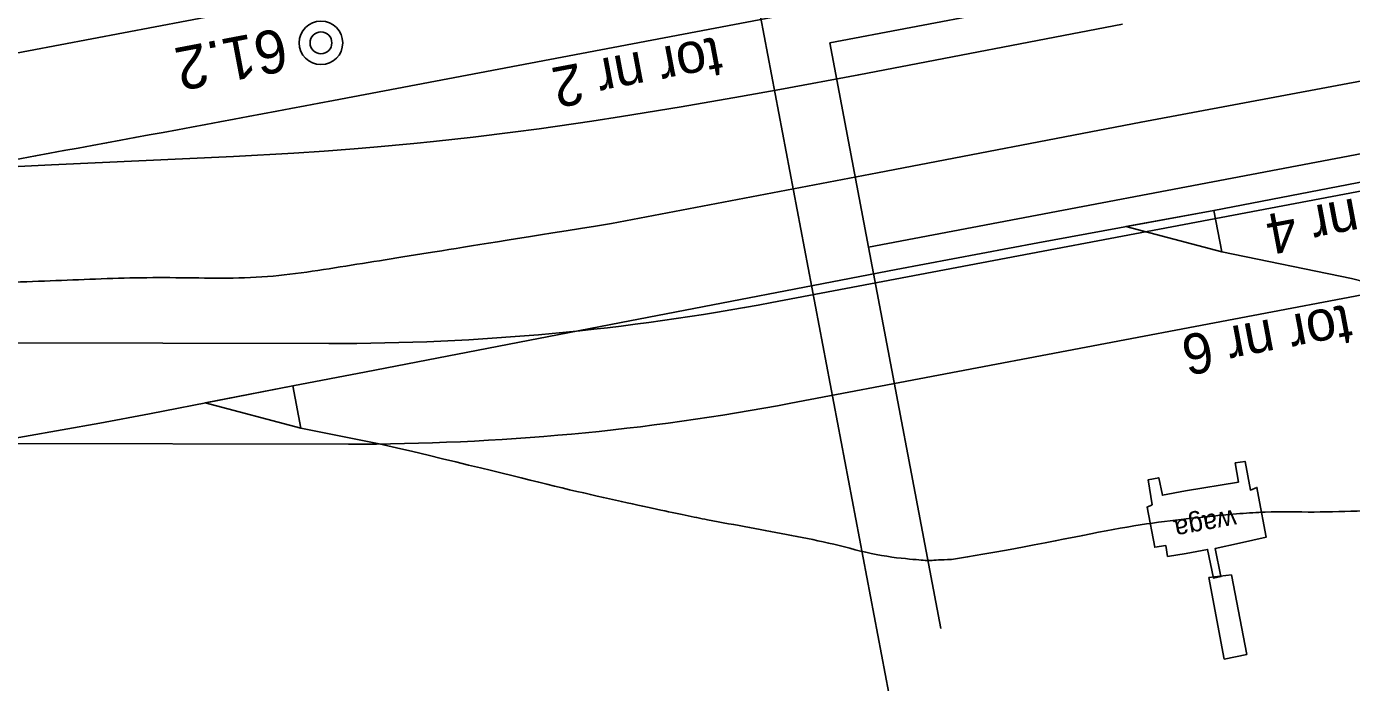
# Model space of a CAD drawing. Extents: x 6541740 to 6566395, y 5525066 to 5530361.
# Drawn here: x 6557260.7 to 6557322.2, y 5526148.2 to 5526178.6 of the extents above; entities that cross this region are included whole.
import ezdxf

# ---------------------------------------------------------------- set-up
doc = ezdxf.new("R2010")
doc.units = 0
for name, color, linetype in [('Domyślna', 7, 'Continuous'), ('ps_wymiarowanie', 7, 'Continuous'), ('TOR_PRZEK_P-komponent', 7, 'Continuous'), ('TOR_PRZEK_P-pomoc', 7, 'Continuous'), ('TOR_PRZEK_P-teren istniejacy', 7, 'Continuous'), ('TOR_PS_ODW-odwodnienie liniowe', 7, 'Continuous'), ('TOR_PS_OPIS_T-opis geometrii-wzdluz_cz torowa', 7, 'Continuous'), ('TOR_PS_T-rowy otwarte nieumocnione', 7, 'Continuous'), ('TOR_RAMKI-ramka+tabelka 1', 7, 'Continuous')]:
    doc.layers.add(name, color=color, linetype=linetype)

# ---------------------------------------------------------------- blocks, each defined once
blk = doc.blocks.new('4010_1')
at = {"layer": 'Domyślna'}
for radius in [0.75, 0.375]:
    blk.add_circle((0, 0), radius, dxfattribs=at)
blk = doc.blocks.new('X KM right')
at = {"layer": 'Domyślna'}
blk.add_line((0, 0), (-16, 0), dxfattribs=at)

msp = doc.modelspace()

# ---------------------------------------------------------------- linework, layer by layer
at = {"layer": 'ps_wymiarowanie'}
for p, q in [((6557315.566, 5526153.102), (6557316.63, 5526153.216)), ((6557315.566, 5526153.102), (6557316.63, 5526153.216)), ((6557316.287, 5526149.311), (6557315.566, 5526153.102)), ((6557316.287, 5526149.311), (6557315.566, 5526153.102)), ((6557316.63, 5526153.216), (6557317.338, 5526149.522)), ((6557316.63, 5526153.216), (6557317.338, 5526149.522)), ((6557317.338, 5526149.522), (6557316.287, 5526149.311)), ((6557317.338, 5526149.522), (6557316.287, 5526149.311))]:
    msp.add_line(p, q, dxfattribs=at)
msp.add_lwpolyline([(6557317.88, 5526156.857), (6557317.805, 5526157.272), (6557317.502, 5526157.146), (6557317.249, 5526158.48), (6557316.794, 5526158.404), (6557316.946, 5526157.519), (6557314.491, 5526157.109), (6557313.419, 5526156.911), (6557313.25, 5526157.717), (6557312.75, 5526157.619), (6557312.94, 5526156.468), (6557312.707, 5526156.36), (6557313.062, 5526154.499), (6557313.572, 5526154.571), (6557313.66, 5526154.074), (6557314.515, 5526154.202), (6557315.514, 5526154.398), (6557315.786, 5526153.071), (6557316.134, 5526153.134), (6557315.87, 5526154.446), (6557316.988, 5526154.684), (6557318.231, 5526154.972)], close=True, dxfattribs=at)
msp.add_lwpolyline([(6557317.88, 5526156.857), (6557317.805, 5526157.272), (6557317.502, 5526157.146), (6557317.249, 5526158.48), (6557316.794, 5526158.404), (6557316.946, 5526157.519), (6557314.491, 5526157.109), (6557313.419, 5526156.911), (6557313.25, 5526157.717), (6557312.75, 5526157.619), (6557312.94, 5526156.468), (6557312.707, 5526156.36), (6557313.062, 5526154.499), (6557313.572, 5526154.571), (6557313.66, 5526154.074), (6557314.515, 5526154.202), (6557315.514, 5526154.398), (6557315.786, 5526153.071), (6557316.134, 5526153.134), (6557315.87, 5526154.446), (6557316.988, 5526154.684), (6557318.231, 5526154.972)], close=True, dxfattribs=at)
at = {"layer": 'TOR_PRZEK_P-komponent'}
for p, q in [((6557416.454, 5526207.025), (6557145.327, 5526155.632)), ((6557373.207, 5526193.841), (6557274.957, 5526175.217)), ((6557371.775, 5526180.338), (6557295.3, 5526165.841)), ((6557367.242, 5526174.644), (6557296.184, 5526161.174)), ((6557274.738, 5526163.945), (6557256.935, 5526163.977)), ((6557275.656, 5526159.278), (6557256.053, 5526159.308))]:
    msp.add_line(p, q, dxfattribs=at)
msp.add_arc((6556891.406, 5528198.665), 2059.479, 280.137444, 280.733239, dxfattribs=at)
for centre, start_param in [((6556974.973, 5527855.75), 3.093771), ((6556975.857, 5527851.083), 3.093849)]:
    msp.add_ellipse(centre, major_axis=(-320.327, 1689.908), ratio=0.25, start_param=start_param, end_param=3.141593, dxfattribs=at)
at = {"layer": 'TOR_PRZEK_P-pomoc'}
for p, q in [((6557347.117, 5526187.205), (6557297.992, 5526177.893)), ((6557347.117, 5526187.205), (6557297.992, 5526177.893)), ((6557297.992, 5526177.893), (6557299.789, 5526168.412)), ((6557297.992, 5526177.893), (6557299.789, 5526168.412)), ((6557299.789, 5526168.412), (6557348.915, 5526177.724)), ((6557299.789, 5526168.412), (6557348.915, 5526177.724))]:
    msp.add_line(p, q, dxfattribs=at)
at = {"layer": 'TOR_PS_OPIS_T-opis geometrii-wzdluz_cz torowa'}
msp.add_line((6557294.428, 5526180.966), (6557304.996, 5526125.216), dxfattribs=at)
at = {"layer": 'TOR_PS_T-rowy otwarte nieumocnione'}
for p, q in [((6557307.636, 5526168.616), (6557315.806, 5526170.117)), ((6557307.636, 5526168.616), (6557315.806, 5526170.117)), ((6557307.636, 5526168.616), (6557315.806, 5526170.117)), ((6557307.636, 5526168.616), (6557315.806, 5526170.117)), ((6557307.636, 5526168.616), (6557315.806, 5526170.117)), ((6557307.636, 5526168.616), (6557315.806, 5526170.117)), ((6557311.721, 5526169.367), (6557316.167, 5526168.203)), ((6557311.721, 5526169.367), (6557316.167, 5526168.203)), ((6557311.721, 5526169.367), (6557316.167, 5526168.203)), ((6557311.721, 5526169.367), (6557316.167, 5526168.203)), ((6557322.19, 5526166.954), (6557329.385, 5526165.171)), ((6557322.19, 5526166.954), (6557329.385, 5526165.171)), ((6557322.19, 5526166.954), (6557329.385, 5526165.171)), ((6557322.19, 5526166.954), (6557329.385, 5526165.171)), ((6557266.418, 5526160.691), (6557273.08, 5526161.976)), ((6557266.418, 5526160.691), (6557273.08, 5526161.976)), ((6557266.418, 5526160.691), (6557273.08, 5526161.975)), ((6557266.418, 5526160.691), (6557273.08, 5526161.975)), ((6557266.418, 5526160.691), (6557273.08, 5526161.975)), ((6557266.418, 5526160.691), (6557273.08, 5526161.975)), ((6557269.001, 5526161.19), (6557273.446, 5526160.026)), ((6557273.446, 5526160.026), (6557269.001, 5526161.19)), ((6557269.001, 5526161.19), (6557273.446, 5526160.026)), ((6557273.446, 5526160.026), (6557269.001, 5526161.19))]:
    msp.add_line(p, q, dxfattribs=at)
for points in [[(6557300.206, 5526171.864), (6557312.429, 5526174.21), (6557325.573, 5526176.668), (6557335.79, 5526178.59), (6557342.216, 5526179.762)], [(6557300.206, 5526171.864), (6557312.429, 5526174.21), (6557325.573, 5526176.668), (6557335.79, 5526178.59), (6557342.216, 5526179.762)], [(6557311.559, 5526178.754), (6557299.33, 5526176.411), (6557299.329, 5526176.411), (6557295.668, 5526175.726), (6557293.836, 5526175.394), (6557291.084, 5526174.914), (6557288.326, 5526174.464), (6557286.944, 5526174.253), (6557286.944, 5526174.253), (6557284.505, 5526173.905), (6557283.283, 5526173.744), (6557281.447, 5526173.519), (6557279.607, 5526173.314), (6557278.686, 5526173.219), (6557276.84, 5526173.046), (6557275.916, 5526172.968), (6557274.527, 5526172.862), (6557274.526, 5526172.862), (6557273.126, 5526172.768), (6557270.317, 5526172.61), (6557261.875, 5526172.232), (6557261.875, 5526172.232), (6557259.395, 5526172.099)], [(6557311.559, 5526178.754), (6557299.33, 5526176.411), (6557299.329, 5526176.411), (6557295.668, 5526175.726), (6557293.836, 5526175.394), (6557291.084, 5526174.914), (6557288.326, 5526174.464), (6557286.944, 5526174.253), (6557286.944, 5526174.253), (6557284.505, 5526173.905), (6557283.283, 5526173.744), (6557281.447, 5526173.519), (6557279.607, 5526173.314), (6557278.686, 5526173.219), (6557276.84, 5526173.046), (6557275.916, 5526172.968), (6557274.527, 5526172.862), (6557274.526, 5526172.862), (6557273.126, 5526172.768), (6557270.317, 5526172.61), (6557261.875, 5526172.232), (6557261.875, 5526172.232), (6557259.395, 5526172.099)], [(6557300.206, 5526171.864), (6557287.861, 5526169.508)], [(6557300.206, 5526171.864), (6557287.861, 5526169.508)], [(6557315.806, 5526170.117), (6557326.46, 5526172.163)], [(6557315.806, 5526170.117), (6557326.46, 5526172.163)], [(6557326.46, 5526172.163), (6557315.806, 5526170.117)], [(6557315.806, 5526170.117), (6557326.46, 5526172.163)], [(6557315.806, 5526170.117), (6557326.46, 5526172.163)], [(6557326.46, 5526172.163), (6557315.806, 5526170.117)], [(6557301.063, 5526167.373), (6557307.636, 5526168.616)], [(6557301.063, 5526167.373), (6557307.636, 5526168.616)], [(6557301.063, 5526167.373), (6557307.636, 5526168.616)], [(6557301.063, 5526167.373), (6557307.636, 5526168.616)], [(6557301.063, 5526167.373), (6557307.636, 5526168.616)], [(6557301.063, 5526167.373), (6557307.636, 5526168.616)], [(6557316.167, 5526168.203), (6557322.19, 5526166.954)], [(6557316.167, 5526168.203), (6557322.19, 5526166.954)], [(6557316.167, 5526168.203), (6557322.19, 5526166.954)], [(6557316.167, 5526168.203), (6557322.19, 5526166.954)], [(6557273.08, 5526161.975), (6557276.479, 5526162.634), (6557288.713, 5526164.999), (6557301.063, 5526167.373)], [(6557273.08, 5526161.975), (6557276.479, 5526162.634), (6557288.713, 5526164.999), (6557301.063, 5526167.373)], [(6557301.063, 5526167.373), (6557288.713, 5526164.999), (6557276.479, 5526162.634), (6557273.08, 5526161.975)], [(6557273.08, 5526161.975), (6557276.479, 5526162.634), (6557288.713, 5526164.999), (6557301.063, 5526167.373)], [(6557273.08, 5526161.975), (6557276.479, 5526162.634), (6557288.713, 5526164.999), (6557301.063, 5526167.373)], [(6557301.063, 5526167.373), (6557288.713, 5526164.999), (6557276.479, 5526162.634), (6557273.08, 5526161.975)], [(6557251.87, 5526158.083), (6557264.115, 5526160.247), (6557266.418, 5526160.691)], [(6557251.87, 5526158.083), (6557264.115, 5526160.247), (6557266.418, 5526160.691)], [(6557266.418, 5526160.691), (6557264.115, 5526160.247), (6557251.87, 5526158.083)], [(6557251.87, 5526158.083), (6557264.115, 5526160.247), (6557266.418, 5526160.691)], [(6557251.87, 5526158.083), (6557264.115, 5526160.247), (6557266.418, 5526160.691)], [(6557266.418, 5526160.691), (6557264.115, 5526160.247), (6557251.87, 5526158.083)], [(6557277.079, 5526159.299), (6557273.446, 5526160.026)], [(6557277.079, 5526159.299), (6557273.446, 5526160.026)], [(6557277.079, 5526159.299), (6557273.446, 5526160.026)], [(6557277.079, 5526159.299), (6557273.446, 5526160.026)]]:
    msp.add_lwpolyline(points, dxfattribs=at)
for points in [[(6557311.721, 5526169.367), (6557315.806, 5526170.117), (6557316.167, 5526168.203)], [(6557311.721, 5526169.367), (6557315.806, 5526170.117), (6557316.167, 5526168.203)], [(6557269.001, 5526161.19), (6557273.08, 5526161.976), (6557273.446, 5526160.026)], [(6557269.001, 5526161.19), (6557273.08, 5526161.976), (6557273.446, 5526160.026)]]:
    msp.add_lwpolyline(points, close=True, dxfattribs=at)
for points in [[(6557250.293, 5526166.395), (6557254.484, 5526166.561), (6557258.675, 5526166.727), (6557262.865, 5526166.893), (6557267.097, 5526167.06), (6557271.394, 5526166.872), (6557275.535, 5526167.535), (6557279.643, 5526168.192), (6557283.752, 5526168.85), (6557287.861, 5526169.508)], [(6557250.293, 5526166.395), (6557254.484, 5526166.561), (6557258.675, 5526166.727), (6557262.865, 5526166.893), (6557267.097, 5526167.06), (6557271.394, 5526166.872), (6557275.535, 5526167.535), (6557279.643, 5526168.192), (6557283.752, 5526168.85), (6557287.861, 5526169.508)], [(6557303.638, 5526153.928), (6557303.117, 5526153.923), (6557302.605, 5526153.864), (6557302.075, 5526153.913), (6557300.155, 5526154.093), (6557298.168, 5526154.668), (6557296.215, 5526155.045), (6557294.262, 5526155.422), (6557292.315, 5526155.757), (6557290.355, 5526156.177), (6557285.945, 5526157.122), (6557281.504, 5526158.258), (6557277.079, 5526159.299)], [(6557277.079, 5526159.299), (6557281.504, 5526158.258), (6557285.945, 5526157.122), (6557290.355, 5526156.177), (6557292.315, 5526155.757), (6557294.262, 5526155.422), (6557296.215, 5526155.045), (6557298.168, 5526154.668), (6557300.155, 5526154.093), (6557302.075, 5526153.913), (6557302.605, 5526153.864), (6557303.117, 5526153.923), (6557303.638, 5526153.928)], [(6557303.638, 5526153.928), (6557303.117, 5526153.923), (6557302.605, 5526153.864), (6557302.075, 5526153.913), (6557300.155, 5526154.093), (6557298.168, 5526154.668), (6557296.215, 5526155.045), (6557294.262, 5526155.422), (6557292.315, 5526155.757), (6557290.355, 5526156.177), (6557285.945, 5526157.122), (6557281.504, 5526158.258), (6557277.079, 5526159.299)], [(6557277.079, 5526159.299), (6557281.504, 5526158.258), (6557285.945, 5526157.122), (6557290.355, 5526156.177), (6557292.315, 5526155.757), (6557294.262, 5526155.422), (6557296.215, 5526155.045), (6557298.168, 5526154.668), (6557300.155, 5526154.093), (6557302.075, 5526153.913), (6557302.605, 5526153.864), (6557303.117, 5526153.923), (6557303.638, 5526153.928)], [(6557332.709, 5526155.658), (6557331.65, 5526155.909), (6557330.566, 5526156.302), (6557329.532, 5526156.41), (6557327.21, 5526156.654), (6557324.997, 5526156.259), (6557322.73, 5526156.183), (6557320.463, 5526156.107), (6557318.169, 5526156.176), (6557315.929, 5526155.956), (6557311.783, 5526155.548), (6557307.735, 5526154.604), (6557303.638, 5526153.928)], [(6557303.638, 5526153.928), (6557307.735, 5526154.604), (6557311.783, 5526155.548), (6557315.929, 5526155.956), (6557318.169, 5526156.176), (6557320.463, 5526156.107), (6557322.73, 5526156.183), (6557324.997, 5526156.259), (6557327.21, 5526156.654), (6557329.532, 5526156.41), (6557330.566, 5526156.302), (6557331.65, 5526155.909), (6557332.709, 5526155.658)], [(6557332.709, 5526155.658), (6557331.65, 5526155.909), (6557330.566, 5526156.302), (6557329.532, 5526156.41), (6557327.21, 5526156.654), (6557324.997, 5526156.259), (6557322.73, 5526156.183), (6557320.463, 5526156.107), (6557318.169, 5526156.176), (6557315.929, 5526155.956), (6557311.783, 5526155.548), (6557307.735, 5526154.604), (6557303.638, 5526153.928)], [(6557303.638, 5526153.928), (6557307.735, 5526154.604), (6557311.783, 5526155.548), (6557315.929, 5526155.956), (6557318.169, 5526156.176), (6557320.463, 5526156.107), (6557322.73, 5526156.183), (6557324.997, 5526156.259), (6557327.21, 5526156.654), (6557329.532, 5526156.41), (6557330.566, 5526156.302), (6557331.65, 5526155.909), (6557332.709, 5526155.658)]]:
    msp.add_open_spline(points, degree=3, dxfattribs=at)

# ---------------------------------------------------------------- block references
at = {"layer": 'TOR_PS_OPIS_T-opis geometrii-wzdluz_cz torowa', "xscale": 1.1250000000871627, "yscale": 1.125000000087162, "rotation": -79.26676346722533}
msp.add_blockref('X KM right', (6557303.141, 5526150.727), dxfattribs=at)
at = {"layer": 'TOR_RAMKI-ramka+tabelka 1', "xscale": 1.345963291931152, "yscale": 1.345963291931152}
msp.add_blockref('4010_1', (6557274.381, 5526177.885), dxfattribs=at)

# ---------------------------------------------------------------- texts
at = {"layer": 'TOR_PRZEK_P-teren istniejacy'}
msp.add_text('waga', height=0.905, rotation=190.34232, dxfattribs=at).set_placement((6557316.755, 5526156.25))
msp.add_text('waga', height=0.905, rotation=190.34232, dxfattribs=at).set_placement((6557316.755, 5526156.25))
at = {"layer": 'TOR_PS_ODW-odwodnienie liniowe'}
for s, p in [('tor nr 2', (6557292.787, 5526178.18)), ('tor nr 4', (6557325.908, 5526171.371)), ('tor nr 6', (6557322.011, 5526165.766))]:
    msp.add_text(s, height=1.875, rotation=190.73324, dxfattribs=at).set_placement(p)
at = {"layer": 'TOR_RAMKI-ramka+tabelka 1'}
msp.add_text('61.2', height=2, rotation=190.76907, dxfattribs=at).set_placement((6557272.597, 5526178.59))

doc.saveas('drawing.dxf')
